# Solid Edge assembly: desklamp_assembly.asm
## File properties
Author: adamb
Template: Iso Metric Assembly.asm
Last saved by: adamb
Revision: 1
Application: Solid Edge
Username: adamb
Dokumentum tartalom típus: 1
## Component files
desklamp_base.par
desklamp_shade.par
desklamp_bulbholder.par
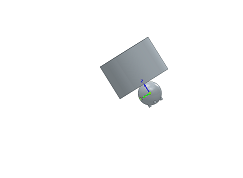
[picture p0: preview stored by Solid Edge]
